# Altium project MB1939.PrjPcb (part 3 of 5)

## Sheet STM32_microcontroller_power.SchDoc: STM32_microcontroller_power
size A4; Date: Not used; ApprovedBy: Not used; CheckedBy: Not used; Author: Not used; CompanyName: STMicroelectronics; DrawnBy: Not used; Engineer: Not used; Organization: Not used; Address1: Not used; Address2: Not used; Address3: Not used; Address4: Not used; DocumentNumber: Not used; Revision: Not used; SheetNumber: 4; SheetTotal: 21
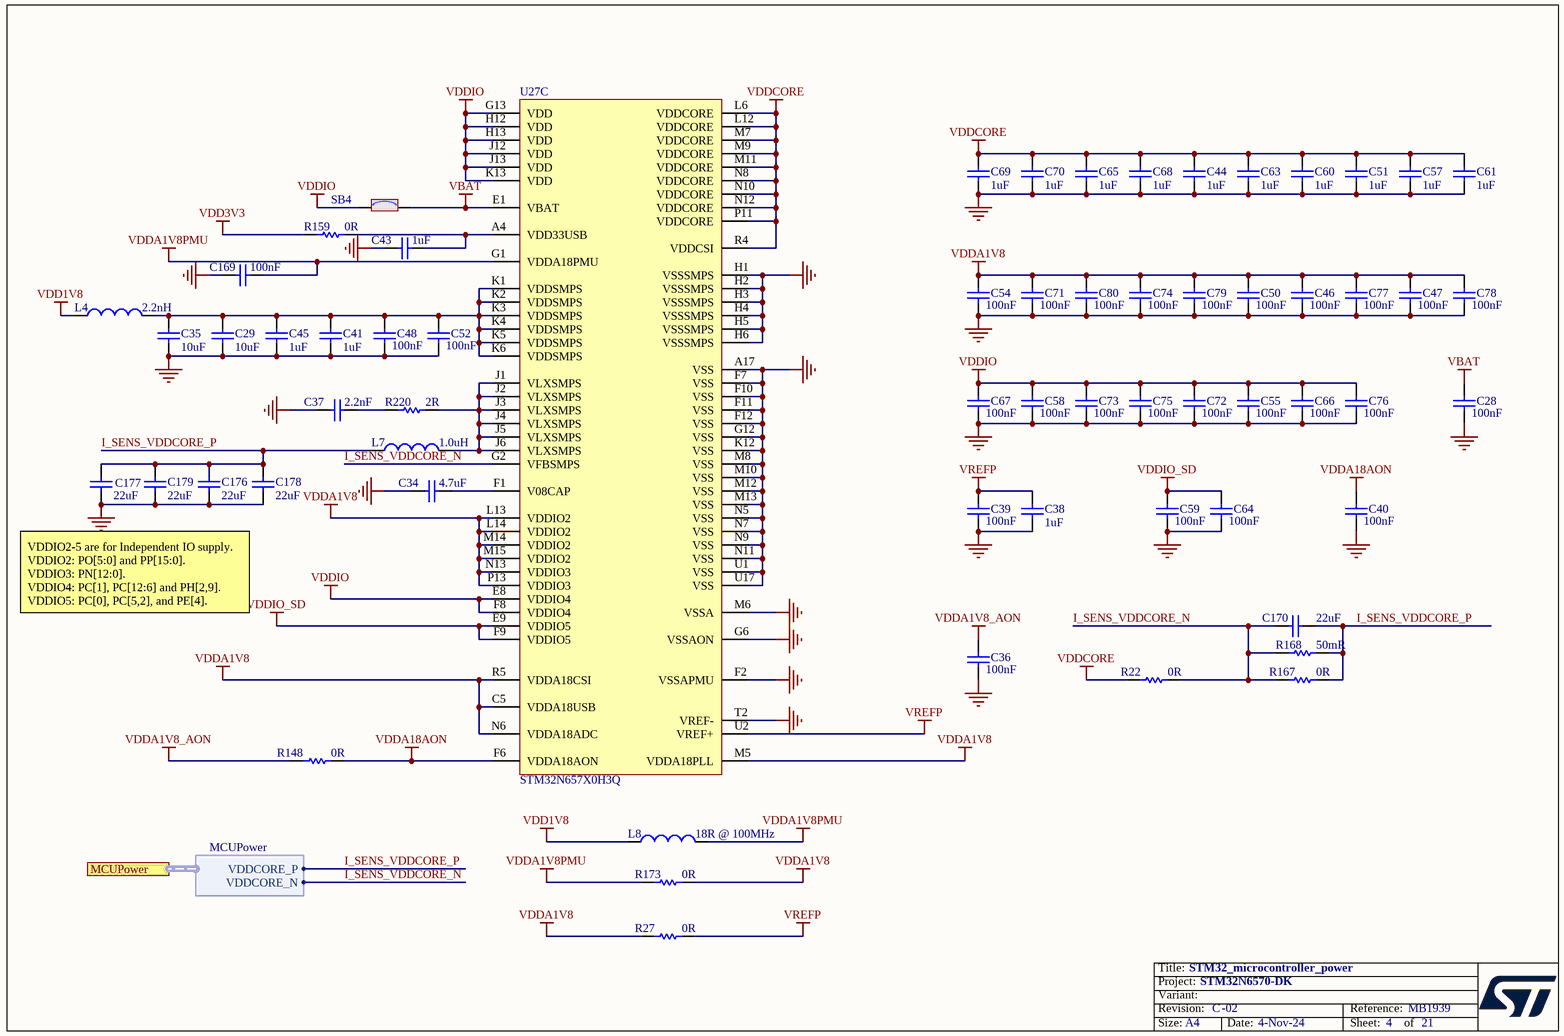
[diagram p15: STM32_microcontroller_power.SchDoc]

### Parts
C28  value 100nF  [C0201_MURATA_GRM033_H0P3]  (hidden comment: Capacitor)
C29  value 10uF  [C0402]  (hidden comment: Capacitor)
C34  value 4.7uF  [C0402]  (hidden comment: Capacitor)
C35  value 10uF  [C0402]  (hidden comment: Capacitor)
C36  value 100nF  [C0201_MURATA_GRM033_H0P3]  (hidden comment: Capacitor)
C37  value 2.2nF  [C0402]  (hidden comment: Capacitor)
C38  value 1uF  [C0201_MURATA_GRM033_H0P3]  (hidden comment: Capacitor)
C39  value 100nF  [C0201_MURATA_GRM033_H0P3]  (hidden comment: Capacitor)
C40  value 100nF  [C0201_MURATA_GRM033_H0P3]  (hidden comment: Capacitor)
C41  value 1uF  [C0201_MURATA_GRM033_H0P3]  (hidden comment: Capacitor)
C43  value 1uF  [C0201_MURATA_GRM033_H0P3]  (hidden comment: Capacitor)
C44  value 1uF  [C0201_MURATA_GRM033_H0P3]  (hidden comment: Capacitor)
C45  value 1uF  [C0201_MURATA_GRM033_H0P3]  (hidden comment: Capacitor)
C46  value 100nF  [C0201_MURATA_GRM033_H0P3]  (hidden comment: Capacitor)
C47  value 100nF  [C0201_MURATA_GRM033_H0P3]  (hidden comment: Capacitor)
C48  value 100nF  [C0201_MURATA_GRM033_H0P3]  (hidden comment: Capacitor)
C50  value 100nF  [C0201_MURATA_GRM033_H0P3]  (hidden comment: Capacitor)
C51  value 1uF  [C0201_MURATA_GRM033_H0P3]  (hidden comment: Capacitor)
C52  value 100nF  [C0201_MURATA_GRM033_H0P3]  (hidden comment: Capacitor)
C54  value 100nF  [C0201_MURATA_GRM033_H0P3]  (hidden comment: Capacitor)
C55  value 100nF  [C0201_MURATA_GRM033_H0P3]  (hidden comment: Capacitor)
C57  value 1uF  [C0201_MURATA_GRM033_H0P3]  (hidden comment: Capacitor)
C58  value 100nF  [C0201_MURATA_GRM033_H0P3]  (hidden comment: Capacitor)
C59  value 100nF  [C0201_MURATA_GRM033_H0P3]  (hidden comment: Capacitor)
C60  value 1uF  [C0201_MURATA_GRM033_H0P3]  (hidden comment: Capacitor)
C61  value 1uF  [C0201_MURATA_GRM033_H0P3]  (hidden comment: Capacitor)
C63  value 1uF  [C0201_MURATA_GRM033_H0P3]  (hidden comment: Capacitor)
C64  value 100nF  [C0201_MURATA_GRM033_H0P3]  (hidden comment: Capacitor)
C65  value 1uF  [C0201_MURATA_GRM033_H0P3]  (hidden comment: Capacitor)
C66  value 100nF  [C0201_MURATA_GRM033_H0P3]  (hidden comment: Capacitor)
C67  value 100nF  [C0201_MURATA_GRM033_H0P3]  (hidden comment: Capacitor)
C68  value 1uF  [C0201_MURATA_GRM033_H0P3]  (hidden comment: Capacitor)
C69  value 1uF  [C0201_MURATA_GRM033_H0P3]  (hidden comment: Capacitor)
C70  value 1uF  [C0201_MURATA_GRM033_H0P3]  (hidden comment: Capacitor)
C71  value 100nF  [C0201_MURATA_GRM033_H0P3]  (hidden comment: Capacitor)
C72  value 100nF  [C0201_MURATA_GRM033_H0P3]  (hidden comment: Capacitor)
C73  value 100nF  [C0201_MURATA_GRM033_H0P3]  (hidden comment: Capacitor)
C74  value 100nF  [C0201_MURATA_GRM033_H0P3]  (hidden comment: Capacitor)
C75  value 100nF  [C0201_MURATA_GRM033_H0P3]  (hidden comment: Capacitor)
C76  value 100nF  [C0201_MURATA_GRM033_H0P3]  (hidden comment: Capacitor)
C77  value 100nF  [C0201_MURATA_GRM033_H0P3]  (hidden comment: Capacitor)
C78  value 100nF  [C0201_MURATA_GRM033_H0P3]  (hidden comment: Capacitor)
C79  value 100nF  [C0201_MURATA_GRM033_H0P3]  (hidden comment: Capacitor)
C80  value 100nF  [C0201_MURATA_GRM033_H0P3]  (hidden comment: Capacitor)
C169  value 100nF  [C0201_MURATA_GRM033_H0P3]  (hidden comment: Capacitor)
C170  value 22uF  [C0603]  (hidden comment: Capacitor)
C176  value 22uF  [C0603]  (hidden comment: Capacitor)
C177  value 22uF  [C0603]  (hidden comment: Capacitor)
C178  value 22uF  [C0603]  (hidden comment: Capacitor)
C179  value 22uF  [C0603]  (hidden comment: Capacitor)
L4  value 2.2nH  [L0603]  (hidden comment: Inductor)
L7  value 1.0uH  [IND_MURATA_DFE201612P]  (hidden comment: Inductor)
L8  value 18R @ 100MHz  [IND_0603_LSMCA_H1P0]  (hidden comment: Inductor)
R22  value 0R  [R0603]  (hidden comment: Resistor)
R27  value 0R  [R0603]  (hidden comment: Resistor)
R148  value 0R  [R0805]  (hidden comment: Resistor)
R159  value 0R  [R0805]  (hidden comment: Resistor)
R167  value 0R  [R0603]  (hidden comment: Resistor)
R168  value 50mR  [R0603]  (hidden comment: Resistor)
R173  value 0R  [R0603]  (hidden comment: Resistor)
R220  value 2R  [R0402]  (hidden comment: Resistor)
SB4  SB_ON  [SOLDER-BRIDGE_R0603-0R]  (value not drawn)
U27  STM32N657X0H3Q  [ICC_VFBGA264_14X14_P080_SOCKET_IRONWOOD_SG-BGA-6112MF]  (part C of 3)

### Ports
MCUPower (harness MCUPower)

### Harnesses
MCUPower: VDDCORE_P, VDDCORE_N

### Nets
GND: C28.1 C29.1 C34.1 C35.1 C36.1 C37.1 C38.1 C39.1 C40.1 C41.1 C43.2 C44.1 C45.1 C46.1 C47.1 C48.1 C50.1 C51.1 C52.1 C54.1 C55.1 C57.1 C58.1 C59.1 C60.1 C61.1 C63.1 C64.1 C65.1 C66.1 C67.1 C68.1 C69.1 C70.1 C71.1 C72.1 C73.1 C74.1 C75.1 C76.1 C77.1 C78.1 C79.1 C80.1 C169.1 C176.1 C177.1 C178.1 C179.1 U27.A17(VSS) U27.F2(VSSAPMU) U27.F7(VSS) U27.F10(VSS) U27.F11(VSS) U27.F12(VSS) U27.G6(VSSAON) U27.G12(VSS) U27.H1(VSSSMPS) U27.H2(VSSSMPS) U27.H3(VSSSMPS) U27.H4(VSSSMPS) U27.H5(VSSSMPS) U27.H6(VSSSMPS) U27.K12(VSS) U27.M6(VSSA) U27.M8(VSS) U27.M10(VSS) U27.M12(VSS) U27.M13(VSS) U27.N5(VSS) U27.N7(VSS) U27.N9(VSS) U27.N11(VSS) U27.T2(VREF-) U27.U1(VSS) U27.U17(VSS)
VBAT: C28.2 SB4.2 U27.E1(VBAT)
VDD1V8: L4.1 L8.1
VDD3V3: R159.1
VDDA1V8: C46.2 C47.2 C50.2 C54.2 C71.2 C74.2 C77.2 C78.2 C79.2 C80.2 R27.1 R173.2 U27.C5(VDDA18USB) U27.L13(VDDIO2) U27.L14(VDDIO2) U27.M5(VDDA18PLL) U27.M14(VDDIO2) U27.M15(VDDIO2) U27.N6(VDDA18ADC) U27.N13(VDDIO3) U27.P13(VDDIO3) U27.R5(VDDA18CSI)
VDDA1V8_AON: C36.2 R148.1
VDDA1V8PMU: C169.2 L8.2 R173.1 U27.G1(VDDA18PMU)
VDDA18AON: C40.2 R148.2 U27.F6(VDDA18AON)
VDDCORE: C44.2 C51.2 C57.2 C60.2 C61.2 C63.2 C65.2 C68.2 C69.2 C70.2 R22.1 U27.L6(VDDCORE) U27.L12(VDDCORE) U27.M7(VDDCORE) U27.M9(VDDCORE) U27.M11(VDDCORE) U27.N8(VDDCORE) U27.N10(VDDCORE) U27.N12(VDDCORE) U27.P11(VDDCORE) U27.R4(VDDCSI)
VDDIO: C55.2 C58.2 C66.2 C67.2 C72.2 C73.2 C75.2 C76.2 SB4.1 U27.E8(VDDIO4) U27.F8(VDDIO4) U27.G13(VDD) U27.H12(VDD) U27.H13(VDD) U27.J12(VDD) U27.J13(VDD) U27.K13(VDD)
VDDIO_SD: C59.2 C64.2 U27.E9(VDDIO5) U27.F9(VDDIO5)
VREFP: C38.2 C39.2 R27.2 U27.U2(VREF+)
I_SENS_VDDCORE_N: C170.2 R22.2 R167.1 R168.1 U27.G2(VFBSMPS) ; port MCUPower.VDDCORE_N  [project net I_SENS_INT_VDDCORE_N]
I_SENS_VDDCORE_P: C170.1 C176.2 C177.2 C178.2 C179.2 L7.1 R167.2 R168.2 ; port MCUPower.VDDCORE_P  [project net I_SENS_INT_VDDCORE_P]
NetC29_2: C29.2 C35.2 C41.2 C45.2 C48.2 C52.2 L4.2 U27.K1(VDDSMPS) U27.K2(VDDSMPS) U27.K3(VDDSMPS) U27.K4(VDDSMPS) U27.K5(VDDSMPS) U27.K6(VDDSMPS)
NetC34_2: C34.2 U27.F1(V08CAP)
NetC37_2: C37.2 R220.1
NetC43_1: C43.1 R159.2 U27.A4(VDD33USB)
NetL7_2: L7.2 R220.2 U27.J1(VLXSMPS) U27.J2(VLXSMPS) U27.J3(VLXSMPS) U27.J4(VLXSMPS) U27.J5(VLXSMPS) U27.J6(VLXSMPS)

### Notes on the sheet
- VDDIO2-5 are for Independent IO supply.             VDDIO2: PO[5:0] and PP[15:0].                                       VDDIO3: PN[12:0].                                               VDDIO4: PC[1], PC[12:6] and PH[2,9].                                        VDDIO5: PC[0], PC[5,2], and PE[4].

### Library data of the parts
C28 C36 C39 C40 C46-C48 C50 C52 C54 C55 C58 C59 C64 C66 C67 C71-C80 C169 = MCD-01535: Capacitor, MLCC,100nF, 10V, X5R, +/-10%, 0201, T=0.3mm; Part_Preference: Recommended; Manufacturer: MURATA; Manufacturer_Part_Number: GRM033R61A104KE15; Order_Code_RS: 790-2742; Component_Country_Of_Origin: Japan°°; ShowFields: YES; ID: 3635
C29 C35 = MCD-01355: Capacitor, MLCC, 10uF, 4V, X5R, +/-20%, 0402, T=0.5mm; Part_Preference: Recommended; Manufacturer: MURATA; Manufacturer_Part_Number: GRM155R60G106ME44; Partial_Alternate_Internal_Part_Number: MCD-01716, MCD-02999; Order_Code_RS: 172-6477; Component_Country_Of_Origin: Japan°°; ShowFields: YES; ID: 3455
C34 = MCD-01356: Capacitor, MLCC, 4.7uF, 6V3, X5R, +/-20%, 0402, T=0.5mm; Part_Preference: Recommended; Manufacturer: MURATA; Manufacturer_Part_Number: GRM155R60J475ME47; Order_Code_RS: 814-5230; Component_Country_Of_Origin: Japan°°; ShowFields: YES; ID: 3456
C37 = MCD-02620: Capacitor, MLCC, 2.2nF, 50V, X7R, +/-10%, 0402, T=0.5mm; Part_Preference: Recommended; Manufacturer: YAGEO; Manufacturer_Part_Number: CC0402KRX7R9BB222; Order_Code_RS: 199-2257; ShowFields: YES; ID: 4726; Component_Country_Of_Origin: China
C38 C41 C43-C45 C51 C57 C60 C61 C63 C65 C68-C70 = MCD-02377: Capacitor, MLCC, 1uF, 6.3V, X5R, +/-20%, 0201, T=0,3mm; Part_Preference: Recommended; Manufacturer: MURATA; Manufacturer_Part_Number: GRM033R60J105MEA2; Order_Code_RS: 820-0643; Component_Country_Of_Origin: Japan°; ShowFields: YES; ID: 4483
C170 = MCD-00100: Capacitor, MLCC, 22uF, 6V3, X5R, +/-20%, 0603, T=0.8mm; Manufacturer_Part_Number: GRM188R60J226MEA0J; Manufacturer: MURATA; Part_Preference: Recommended; Component_Country_Of_Origin: Japan°°; ShowFields: YES; ID: 2766
C176-C179 = MCD-00100: Capacitor, MLCC, 22uF, 6V3, X5R, +/-20%, 0603, T=0.8mm; Part_Preference: Recommended; Manufacturer: MURATA; Manufacturer_Part_Number: GRM188R60J226MEA0J; Component_Country_Of_Origin: Japan°°; ShowFields: YES; ID: 2766
L4 = MCD-03222: Inductor, 2.2nH, +/-0.5nH, Irat=1.4Amax, 0R018, 0603, T=1mm, Qmin=25; Part_Preference: Recommended; Manufacturer: MURATA; Manufacturer_Part_Number: LQW18AN2N2D10D; ShowFields: YES; ID: 5338; Component_Country_Of_Origin: Malaysia
L7 = MCD-01491: Inductor, 1uH, +/-20%, Itemp= 2700mA, Isat= 3300mA, 0R054, 0806, T=1mm; Part_Preference: Recommended; Manufacturer: MURATA; Manufacturer_Part_Number: DFE201612P-1R0M; Order_Code_RS: 167-0602; Component_Country_Of_Origin: Japan°°; ShowFields: YES; ID: 3591
L8 = MCD-03956: Ferrite bead, 18R @ 100MHz, 750mA, 0R004, 0603, T=1mm; Part_Preference: Recommended; Manufacturer: TAIYO YUDEN; Manufacturer_Part_Number: LSMCA160808T180NGR; Component_Country_Of_Origin: Unknown; ShowFields: YES; ID: 6072
R22 R27 R167 R173 = MCD-00181: Resistor, 0R, 0603, +/- 0.5mR, 1/4W; Manufacturer_Part_Number: PMR03EZPJ000; Manufacturer: ROHM SEMICONDUCTOR; Part_Preference: Recommended; Component_Country_Of_Origin: Philippines, Thailand°°; ShowFields: YES; ID: 2691
R148 R159 = MCD-00179: Resistor, 0R, 0805, +/-5%, 1/8W; Part_Preference: Recommended; Manufacturer: YAGEO; Manufacturer_Part_Number: RC0805JR-070RL; Component_Country_Of_Origin: China; ShowFields: YES; ID: 2685
R168 = MCD-02233: Resistor, 50mR, 0603, +/-1%, 1/3W; Part_Preference: Recommended; Manufacturer: PANASONIC; Manufacturer_Part_Number: ERJ-3BWFR050V; Order_Code_RS: RA; Component_Country_Of_Origin: Japan; ShowFields: YES; ID: 4333
R220 = MCD-03930: Resistor, 2R, 0402, +/-1%, 1/16W; Part_Preference: Recommended; Manufacturer: YAGEO; Manufacturer_Part_Number: RC0402FR-072RL; ShowFields: YES; ID: 6046; Component_Country_Of_Origin: China
SB4 = MCD-00071: Resistor, 0R, SB0603, 5%, 0.1W; Manufacturer_Part_Number: RC0603JR-070RL; Manufacturer: YAGEO; Part_Preference: Recommended; Manufacturer_HQ_COO: Unknown; ShowFields: YES; ID: 2521; Order_Code_RS: 199-5647; Component_Country_Of_Origin: China
U27 = MCD-03176: Neural MCU, Arm® Cortex®-M55, 600-Gops ST Neural-ART Accelerator, Neo-Chrom 2.5D GPU, 4.2 MB contiguous SRAM; Part_Type: IC; Part_Preference: Recommended; Manufacturer: STMICROELECTRONICS; ShowFields: YES; ID: 5292; Component_Country_Of_Origin: Unknown

## Sheet Audio_Codec.SchDoc: Audio_Codec
size A4; Date: Not used; ApprovedBy: Not used; CheckedBy: Not used; Author: Not used; CompanyName: STMicroelectronics; DrawnBy: Not used; Engineer: Not used; Organization: Not used; Address1: Not used; Address2: Not used; Address3: Not used; Address4: Not used; DocumentNumber: Not used; Revision: Not used; SheetNumber: 15; SheetTotal: 21
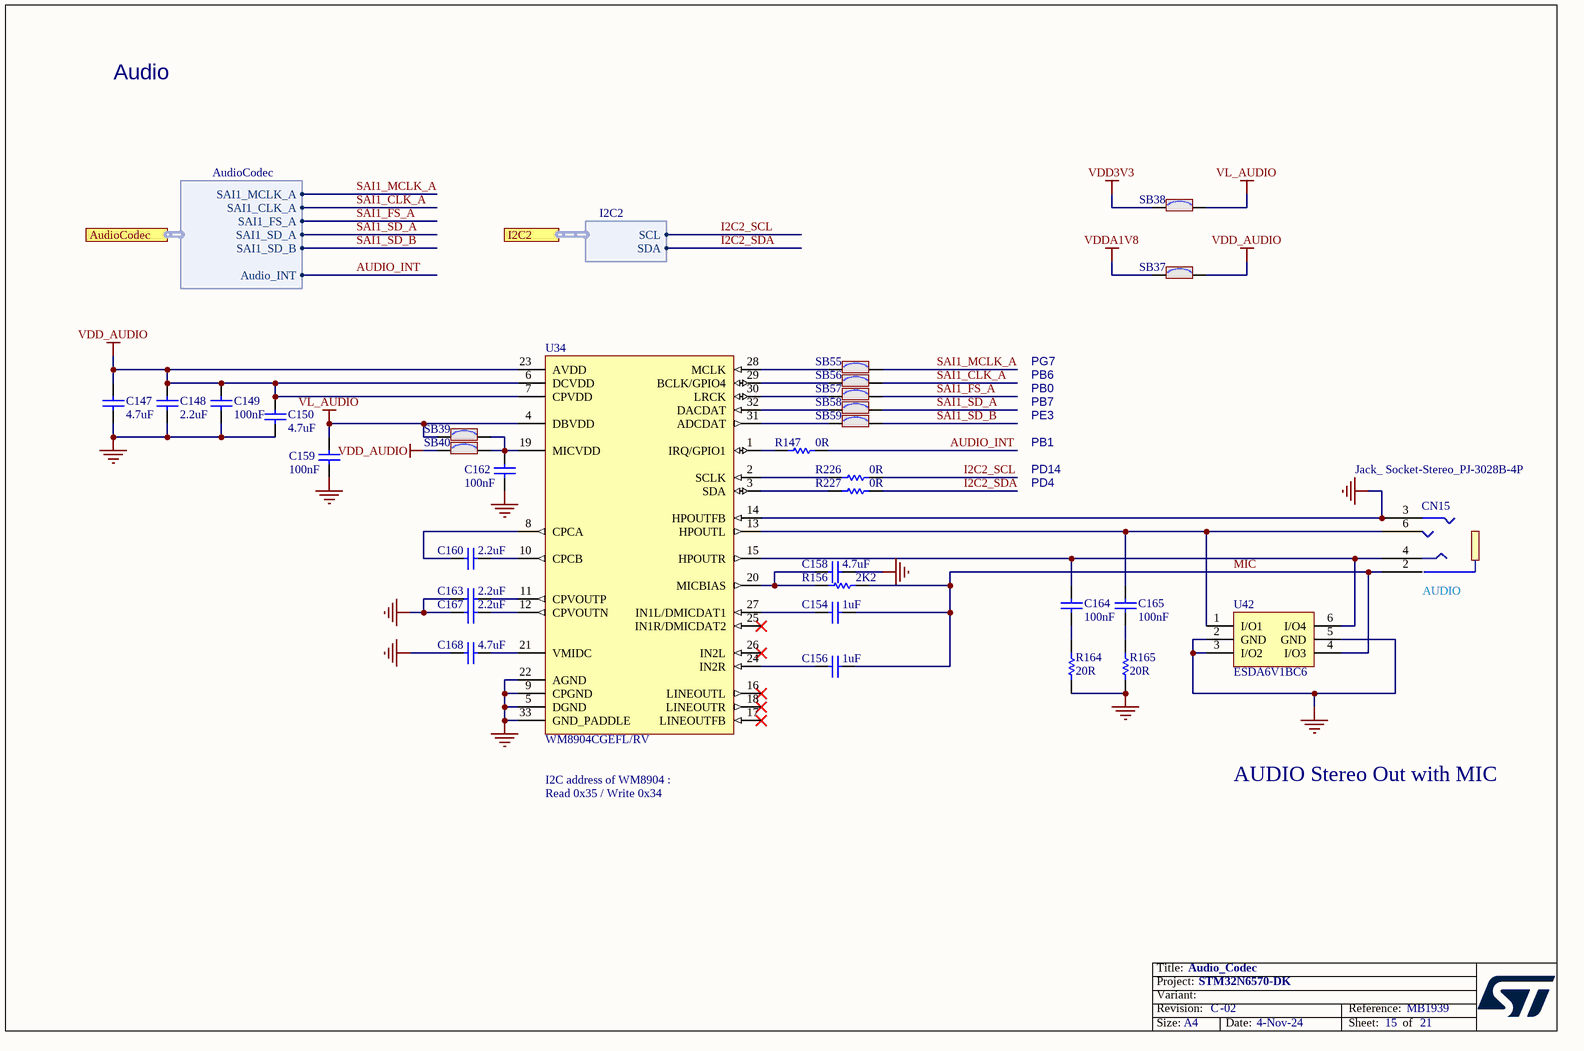
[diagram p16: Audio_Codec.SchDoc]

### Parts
C147  value 4.7uF  [C0603]  (hidden comment: Capacitor)
C148  value 2.2uF  [C0603]  (hidden comment: Capacitor)
C149  value 100nF  [C0402]  (hidden comment: Capacitor)
C150  value 4.7uF  [C0603]  (hidden comment: Capacitor)
C154  value 1uF  [C0603]  (hidden comment: Capacitor)
C156  value 1uF  [C0603]  (hidden comment: Capacitor)
C158  value 4.7uF  [C0603]  (hidden comment: Capacitor)
C159  value 100nF  [C0402]  (hidden comment: Capacitor)
C160  value 2.2uF  [C0603]  (hidden comment: Capacitor)
C162  value 100nF  [C0402]  (hidden comment: Capacitor)
C163  value 2.2uF  [C0603]  (hidden comment: Capacitor)
C164  value 100nF  [C0402]  (hidden comment: Capacitor)
C165  value 100nF  [C0402]  (hidden comment: Capacitor)
C167  value 2.2uF  [C0603]  (hidden comment: Capacitor)
C168  value 4.7uF  [C0603]  (hidden comment: Capacitor)
CN15  value Jack_ Socket-Stereo_PJ-3028B-4P  [CON_PHONE-JACK-3P5_HY_PJ3028B]  (hidden comment: Jack_PJ3028B-3_4P)
R147  value 0R  [R0603]  (hidden comment: Resistor)
R156  value 2K2  [R0402]  (hidden comment: Resistor)
R164  value 20R  [R0603]  (hidden comment: Resistor)
R165  value 20R  [R0603]  (hidden comment: Resistor)
R226  value 0R  [R0402]  (hidden comment: Resistor)
R227  value 0R  [R0402]  (hidden comment: Resistor)
SB37  SB_ON  [SOLDER-BRIDGE_R0402-0R]  (value not drawn)
SB38  SB_ON  [SOLDER-BRIDGE_R0402-0R]  (value not drawn)
SB39  SB_ON  [SOLDER-BRIDGE_R0402-0R]  (value not drawn)
SB40  SB_ON  [SOLDER-BRIDGE_R0402-0R]  (value not drawn)
SB55  SB_ON  [SOLDER-BRIDGE_R0402-0R]  (value not drawn)
SB56  SB_ON  [SOLDER-BRIDGE_R0402-0R]  (value not drawn)
SB57  SB_ON  [SOLDER-BRIDGE_R0402-0R]  (value not drawn)
SB58  SB_ON  [SOLDER-BRIDGE_R0402-0R]  (value not drawn)
SB59  SB_ON  [SOLDER-BRIDGE_R0402-0R]  (value not drawn)
U34  WM8904CGEFL/RV  [ICC_QFN32-EPAD_4X4_P040]
U42  ESDA6V1BC6  [ESD_SOT23-6L]

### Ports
AudioCodec (harness AudioCodec), I2C2 (harness I2C2)

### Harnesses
I2C2: SCL, SDA
AudioCodec: SAI1_MCLK_A, SAI1_CLK_A, SAI1_FS_A, SAI1_SD_A, SAI1_SD_B, Audio_INT

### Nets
GND: C147.1 C148.1 C149.1 C150.1 C158.2 C159.1 C162.1 C163.2 C167.2 C168.1 CN15.3 R164.1 R165.1 U34.5(DGND) U34.9(CPGND) U34.14(HPOUTFB) U34.22(AGND) U34.33(GND_PADDLE) U42.2(GND) U42.3(I/O2) U42.5(GND)
VDD3V3: SB38.1
VDD_AUDIO: C147.2 C148.2 C149.2 C150.2 SB37.2 SB40.1 U34.6(DCVDD) U34.7(CPVDD) U34.23(AVDD)
VDDA1V8: SB37.1
VL_AUDIO: C159.2 SB38.2 SB39.1 U34.4(DBVDD)
AUDIO_INT: R147.2 ; port AudioCodec.Audio_INT
I2C2_SCL: R226.2 ; port I2C2.SCL
I2C2_SDA: R227.2 ; port I2C2.SDA
MIC: C154.2 C156.2 CN15.2 R156.1 U42.4(I/O3)
SAI1_CLK_A: SB56.2 ; port AudioCodec.SAI1_CLK_A  [project net PB6]
SAI1_FS_A: SB57.2 ; port AudioCodec.SAI1_FS_A  [project net PB0]
SAI1_MCLK_A: SB55.2 ; port AudioCodec.SAI1_MCLK_A  [project net PG7]
SAI1_SD_A: SB58.2 ; port AudioCodec.SAI1_SD_A  [project net PB7]
SAI1_SD_B: SB59.2 ; port AudioCodec.SAI1_SD_B  [project net PE3]
NetC154_1: C154.1 U34.27(IN1L/DMICDAT1)
NetC156_1: C156.1 U34.24(IN2R)
NetC158_1: C158.1 R156.2 U34.20(MICBIAS)
NetC160_1: C160.1 U34.10(CPCB)
NetC160_2: C160.2 U34.8(CPCA)
NetC162_2: C162.2 SB39.2 SB40.2 U34.19(MICVDD)
NetC163_1: C163.1 U34.11(CPVOUTP)
NetC164_1: C164.1 CN15.4 U34.15(HPOUTR) U42.6(I/O4)
NetC164_2: C164.2 R164.2
NetC165_1: C165.1 CN15.6 U34.13(HPOUTL) U42.1(I/O1)
NetC165_2: C165.2 R165.2
NetC167_1: C167.1 U34.12(CPVOUTN)
NetC168_2: C168.2 U34.21(VMIDC)
NetR147_1: R147.1 U34.1(IRQ/GPIO1)
NetR226_1: R226.1 U34.2(SCLK)
NetR227_1: R227.1 U34.3(SDA)
NetSB55_1: SB55.1 U34.28(MCLK)
NetSB56_1: SB56.1 U34.29(BCLK/GPIO4)
NetSB57_1: SB57.1 U34.30(LRCK)
NetSB58_1: SB58.1 U34.32(DACDAT)
NetSB59_1: SB59.1 U34.31(ADCDAT)

Not connected (* = marked no-connect by the designer): U34 16(LINEOUTL)* 17(LINEOUTFB)* 18(LINEOUTR)* 25(IN1R/DMICDAT2)* 26(IN2L)*

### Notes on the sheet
- Audio
- PG7
- PB6
- PB0
- PB7
- PE3
- PB1
- PD14
- PD4
- (near CN15) AUDIO
- I2C address of WM8904 :
- AUDIO Stereo Out with MIC
- Read 0x35 / Write 0x34
- Title:
- Project:
- Size:
- Revision:
- Variant:
- A4
- -
- Date:
- Reference:
- Sheet:
- of

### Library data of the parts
C147 C150 C158 C168 = MCD-00009: Capacitor, MLCC, 4.7uF, 16V, X5R, +/-10%, 0603, T=0.8mm; Part_Preference: Recommended; Manufacturer: YAGEO; Manufacturer_Part_Number: CC0603KRX5R7BB475; Partial_Alternate_Internal_Part_Number: MCD-03565; Component_Country_Of_Origin: China; Alternate_EMS: A; ShowFields: YES; ID: 2471
C148 C160 C163 C167 = MCD-00012: Capacitor, MLCC, 2.2uF, 10V, X5R, +/- 10%, 0603, T=0.8mm; BMS_Part_Number: 9142010; Part_Preference: Recommended; Manufacturer: YAGEO; Manufacturer_Part_Number: CC0603KRX5R6BB225; Partial_Alternate_Internal_Part_Number: MCD-00551; Order_Code_RS: 2370679; Component_Country_Of_Origin: China; ShowFields: YES; ID: 2467
C149 C159 C162 C164 C165 = MCD-00006: Capacitor, MLCC, 100nF, 16V, X7R, +/-10%, 0402, T=0.5mm; Manufacturer_Part_Number: CC0402KRX7R7BB104; Manufacturer: YAGEO; Part_Preference: Recommended; Partial_Alternate_Internal_Part_Number: MCD-03299; Order_Code_RS: 9402047; Component_Country_Of_Origin: China; ShowFields: YES; ID: 2474
C154 C156 = MCD-00010: Capacitor, MLCC, 1uF, 16V, X5R, +/-10%, 0603, T=0.8mm; Manufacturer_Part_Number: CC0603KRX5R7BB105; Manufacturer: YAGEO; Part_Preference: Recommended; Order_Code_RS: 2370680; Component_Country_Of_Origin: China; ShowFields: YES; ID: 2470
CN15 = MCD-00263: Jack_ Socket-Stereo, 3.5mm, 4 pins, RA, SMD, T=5mm; Part_Type: Connector; Manufacturer_Part_Number: PJ-3028B-4P; Manufacturer: QIAOD; Part_Preference: Recommended; Component_Country_Of_Origin: Unknown; ShowFields: YES; ID: 2608
R147 = MCD-00056: Resistor, 0R, 0603, +/-5%, 1/10W; Part_Preference: Recommended; Manufacturer: YAGEO; Manufacturer_Part_Number: RC0603JR-070RL; Order_Code_RS: 9233130RL; Component_Country_Of_Origin: China; ShowFields: YES; ID: 2536
R156 = MCD-00057: Resistor, 2K2, 0402, +/-1%, 1/16W; Manufacturer_Part_Number: RC0402FR-072K2L; Manufacturer: YAGEO; Part_Preference: Recommended; Order_Code_RS: 9239278; Component_Country_Of_Origin: China; ShowFields: YES; ID: 2534
R164 R165 = MCD-00345: Resistor, 20R, 0603, +/-1%, 1/10W; Part_Preference: Recommended; Manufacturer: YAGEO; Manufacturer_Part_Number: RC0603FR-0720RL; Component_Country_Of_Origin: China; ShowFields: YES; ID: 2933
R226 R227 = MCD-00052: Resistor, 0R, 0402, +/-5%, 1/16W; Manufacturer_Part_Number: RC0402JR-070RL; Manufacturer: YAGEO; Part_Preference: Recommended; Order_Code_RS: 9232516RL; Component_Country_Of_Origin: China; ShowFields: YES; ID: 2540
SB37-SB40 SB55-SB59 = MCD-01618: Resistor, 0R, SB0402, 5%, 0.063W; Manufacturer_Part_Number: RC0402JR-070RL; Manufacturer: YAGEO; Part_Preference: Recommended; Order_Code_RS: 618-5804; Component_Country_Of_Origin: China; ShowFields: YES; ID: 3718
U34 = MCD-03825: Audio Codec, Ultra Low-Power Codec for Portable Audio Applications; Part_Type: IC; Part_Preference: Recommended; Manufacturer: CIRRUS LOGIC; ShowFields: YES; ID: 5941; Component_Country_Of_Origin: Taiwan
U42 = MCD-00247: Diode, ESD Transil, 5V, 1uA, 8V, SOT23-6; Manufacturer: STMICROELECTRONICS; BMS_Part_Number: 9179038; Part_Preference: Recommended; Manufacturer_HQ_COO: EU; Component_Country_Of_Origin: China; ShowFields: YES; ID: 2624; Order_Code_RS: 248-805

## Sheet USB1_DRP.SchDoc: USB1_DRP
size A3; Date: Not used; ApprovedBy: Not used; CheckedBy: Not used; Author: Not used; CompanyName: STMicroelectronics; DrawnBy: Not used; Engineer: Not used; Organization: Not used; Address1: Not used; Address2: Not used; Address3: Not used; Address4: Not used; DocumentNumber: Not used; Revision: Not used; SheetNumber: 17; SheetTotal: 21
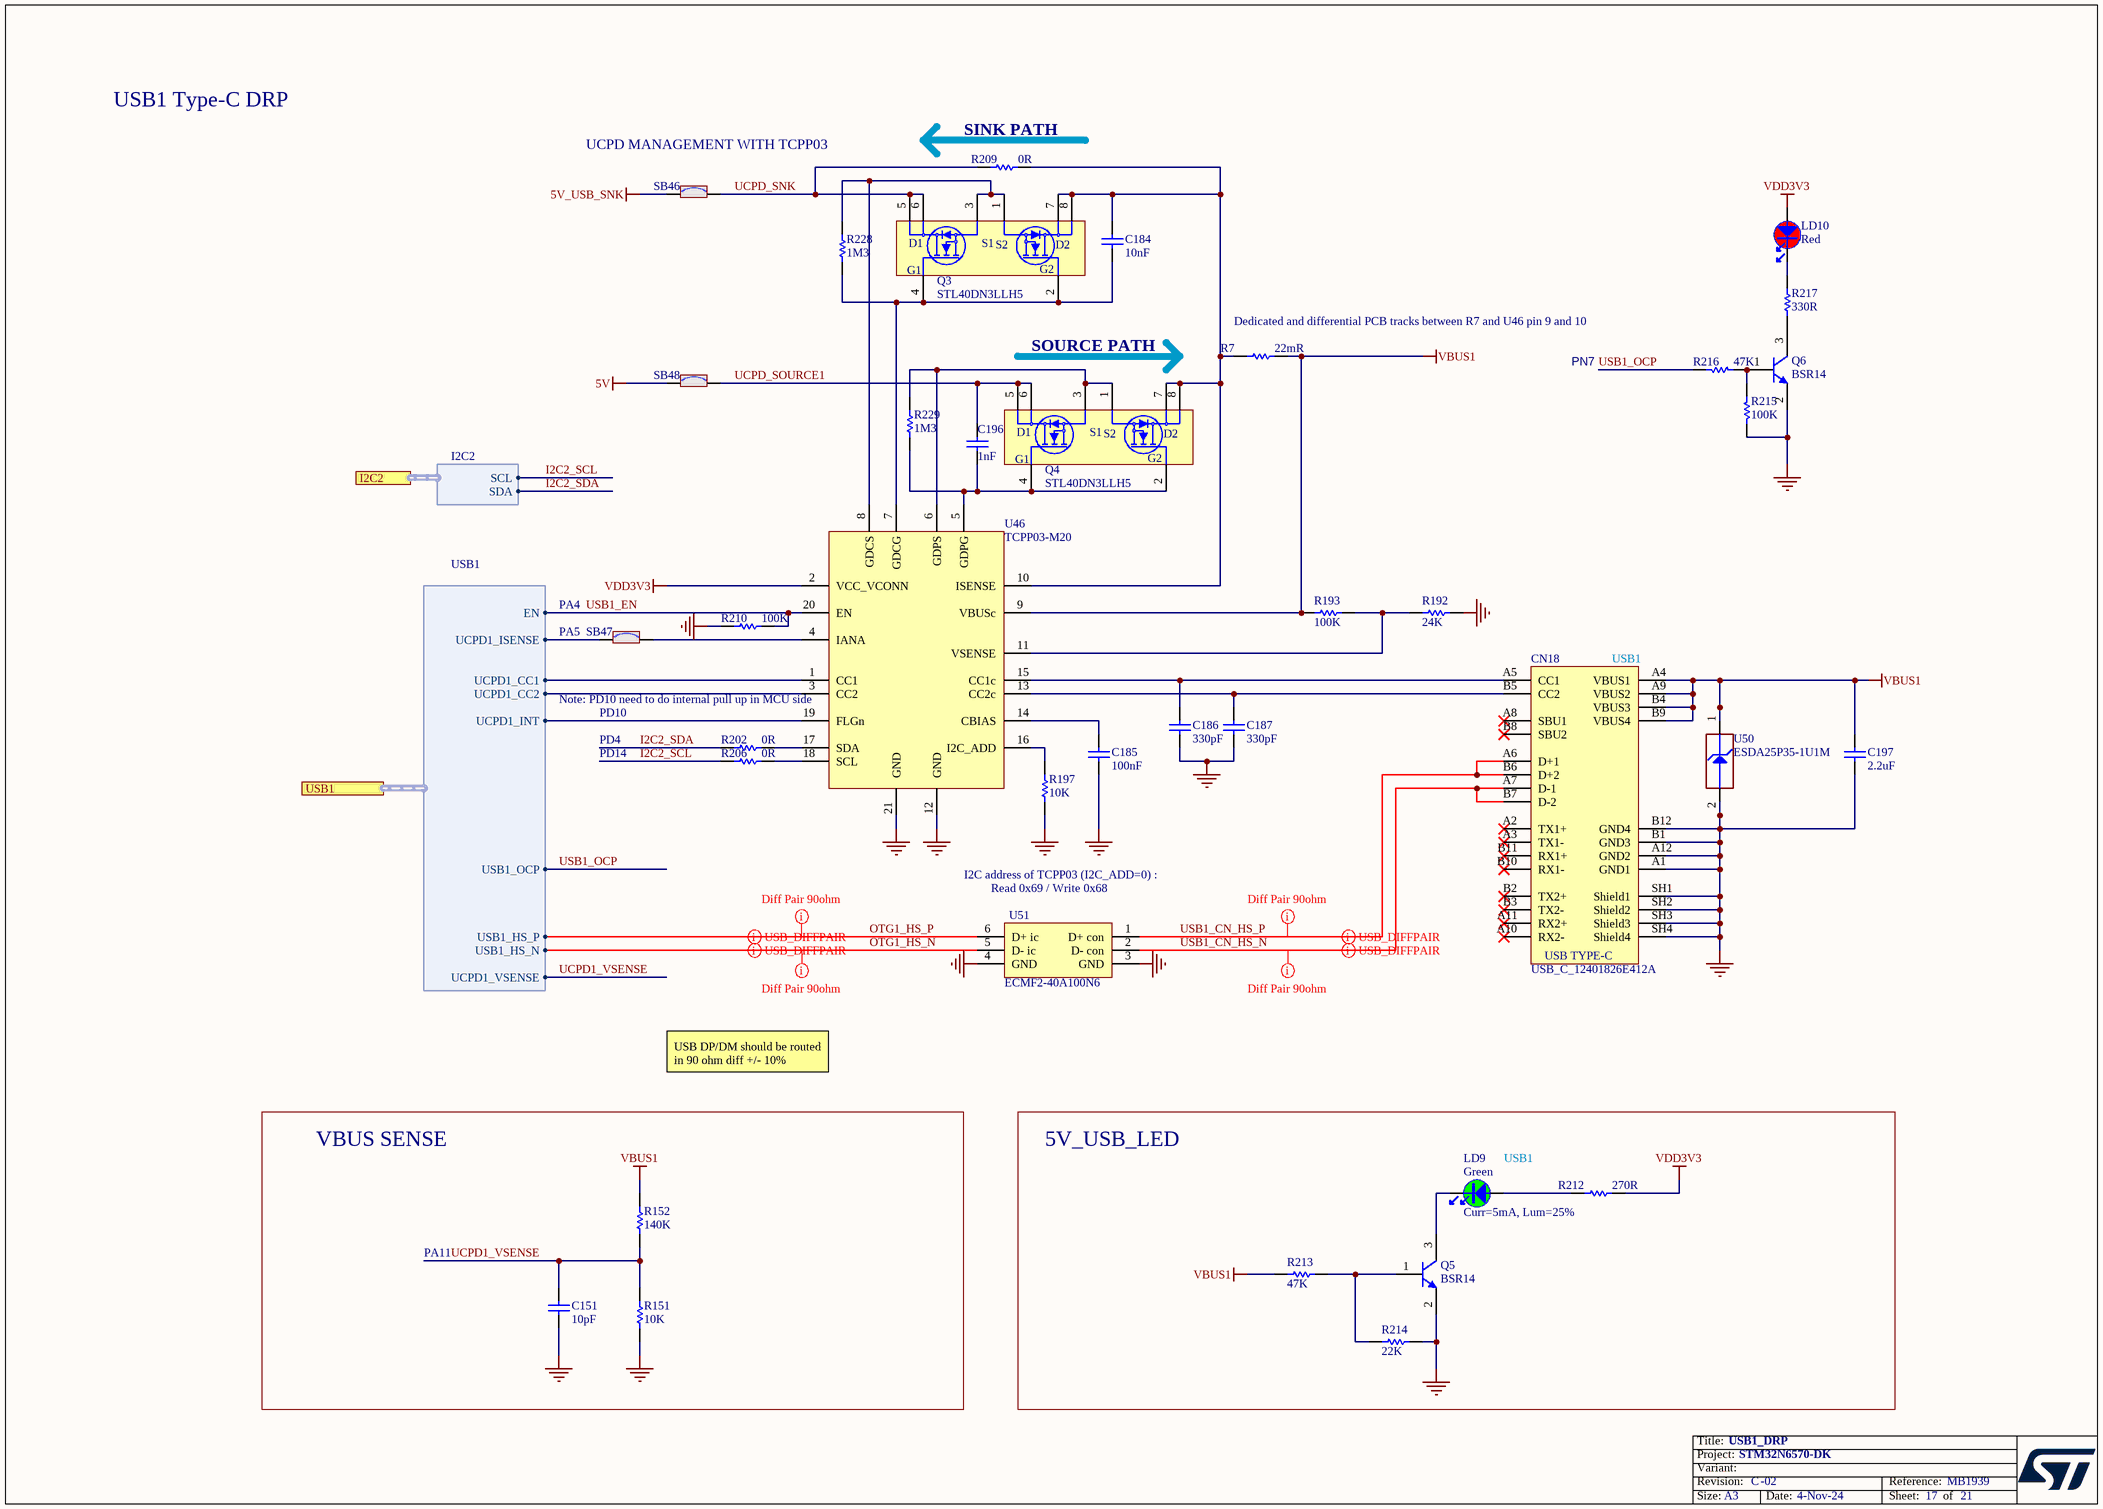
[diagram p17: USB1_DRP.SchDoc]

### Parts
C151  value 10pF  [C0402]  (hidden comment: Capacitor)
C184  value 10nF  [C0402]  (hidden comment: Capacitor)
C185  value 100nF  [C0603]  (hidden comment: Capacitor)
C186  value 330pF  [C0402]  (hidden comment: Capacitor)
C187  value 330pF  [C0402]  (hidden comment: Capacitor)
C196  value 1nF  [C0805_H0P6]  (hidden comment: Capacitor)
C197  value 2.2uF  [C0805]  (hidden comment: Capacitor)
CN18  value USB_C_12401826E412A  [CON_USB-TYPEC_AMPHENOL_12401826E412A]  (hidden comment: USB_TYPE_C_Receptacle)
LD9  value Green  [LED_0603_OSRAM_LG-Q396-PS-35_GREEN_1A2K_H0P4]  (hidden comment: LED_green)
LD10  value Red  [LED_0603_VISHAY_VLMS1300-GS08_RED_1A2K_H0P8]  (hidden comment: LED_red)
Q3  STL40DN3LLH5  [PowerFLAT_5x6]
Q4  STL40DN3LLH5  [PowerFLAT_5x6]
Q5  value BSR14  [NPN_SOT23]  (hidden comment: 9013-SOT23)
Q6  value BSR14  [NPN_SOT23]  (hidden comment: 9013-SOT23)
R7  value 22mR  [R0603]  (hidden comment: Resistor)
R151  value 10K  [R0402]  (hidden comment: Resistor)
R152  value 140K  [R0402]  (hidden comment: Resistor)
R192  value 24K  [R0402]  (hidden comment: Resistor)
R193  value 100K  [R0402]  (hidden comment: Resistor)
R197  value 10K  [R0402]  (hidden comment: Resistor)
R202  value 0R  [R0402]  (hidden comment: Resistor)
R206  value 0R  [R0402]  (hidden comment: Resistor)
R209  value 0R  [R0603]  (hidden comment: Resistor)
R210  value 100K  [R0402]  (hidden comment: Resistor)
R212  value 270R  [R0402]  (hidden comment: Resistor)
R213  value 47K  [R0402]  (hidden comment: Resistor)
R214  value 22K  [R0603]  (hidden comment: Resistor)
R215  value 100K  [R0402]  (hidden comment: Resistor)
R216  value 47K  [R0402]  (hidden comment: Resistor)
R217  value 330R  [R0402]  (hidden comment: Resistor)
R228  value 1M3  [R0402]  (hidden comment: Resistor)
R229  value 1M3  [R0402]  (hidden comment: Resistor)
SB46  SB_ON  [SOLDER-BRIDGE_R0603-0R]  (value not drawn)
SB47  SB_ON  [SOLDER-BRIDGE_R0603-0R]  (value not drawn)
SB48  SB_ON  [SOLDER-BRIDGE_R0603-0R]  (value not drawn)
U46  TCPP03-M20  [ICC_QFN20-EPAD_4X4_P050]
U50  value ESDA25P35-1U1M  [ESD_QFN1610_2N_1K_2A]  (hidden comment: ESD-TRANSIL)
U51  ECMF2-40A100N6  [ESD_UQFN-6L_1P45X1P4_P040]

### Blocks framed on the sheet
VBUS SENSE: C151 R151 R152
5V_USB_LED: LD9 Q5 R212-R214

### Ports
I2C2 (harness I2C2), USB1 (harness USB1)

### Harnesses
USB1: UCPD1_CC1, UCPD1_CC2, UCPD1_ISENSE, USB1_HS_P, USB1_HS_N, UCPD1_VSENSE, UCPD1_INT, USB1_OCP, EN
I2C2: SCL, SDA

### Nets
5V: SB48.1
5V_USB_SNK: SB46.1
GND: C151.1 C185.2 C186.1 C187.1 C197.1 CN18.A1(GND1) CN18.A12(GND2) CN18.B1(GND3) CN18.B12(GND4) CN18.SH1(Shield1) CN18.SH2(Shield2) CN18.SH3(Shield3) CN18.SH4(Shield4) Q5.2(E) Q6.2(E) R151.1 R192.2 R197.2 R210.1 R214.2 R215.1 U46.12(GND) U46.21(GND) U50.2(GND) U51.3(GND) U51.4(GND)
VBUS1: C197.2 CN18.A4(VBUS1) CN18.A9(VBUS2) CN18.B4(VBUS3) CN18.B9(VBUS4) R7.2 R152.2 R193.1 R213.1 U46.9(VBUSc) U50.1(IO1)
VDD3V3: LD10.1 R212.1 U46.2(VCC_VCONN)
ARD_A0: SB47.1 ; port USB1.UCPD1_ISENSE
I2C2_SCL: R206.1 ; port I2C2.SCL
I2C2_SDA: R202.1 ; port I2C2.SDA
OTG1_HS_N: U51.5(D-_ic) ; port USB1.USB1_HS_N
OTG1_HS_P: U51.6(D+_ic) ; port USB1.USB1_HS_P
PD10: U46.19(FLGn) ; port USB1.UCPD1_INT
UCPD1_CC1: U46.1(CC1) ; port USB1.UCPD1_CC1
UCPD1_CC2: U46.3(CC2) ; port USB1.UCPD1_CC2
UCPD1_VSENSE: C151.2 R151.2 R152.1 ; port USB1.UCPD1_VSENSE  [project net PA11]
UCPD_SNK: Q3.5(D1) Q3.6(D1) R209.1 SB46.2
UCPD_SOURCE1: C196.1 Q4.5(D1) Q4.6(D1) SB48.2
USB1_CN_HS_N: CN18.A7(D-1) CN18.B7(D-2) U51.2(D-_con)
USB1_CN_HS_P: CN18.A6(D+1) CN18.B6(D+2) U51.1(D+_con)
USB1_EN: R210.2 U46.20(EN) ; port USB1.EN  [project net PA4]
USB1_OCP: R216.2 ; port USB1.USB1_OCP  [project net PN7]
NetC184_1: C184.1 Q3.7(D2) Q3.8(D2) Q4.7(D2) Q4.8(D2) R7.1 R209.2 U46.10(ISENSE)
NetC184_2: C184.2 Q3.2(G2) Q3.4(G1) R228.1 U46.7(GDCG)
NetC185_1: C185.1 U46.14(CBIAS)
NetC186_2: C186.2 CN18.A5(CC1) U46.15(CC1c)
NetC187_2: C187.2 CN18.B5(CC2) U46.13(CC2c)
NetC196_2: C196.2 Q4.2(G2) Q4.4(G1) R229.1 U46.5(GDPG)
NetLD9_1: LD9.1 R212.2
NetLD9_2: LD9.2 Q5.3(C)
NetLD10_2: LD10.2 R217.2
NetQ3_1: Q3.1(S2) Q3.3(S1) R228.2 U46.8(GDCS)
NetQ4_1: Q4.1(S2) Q4.3(S1) R229.2 U46.6(GDPS)
NetQ5_1: Q5.1(B) R213.2 R214.1
NetQ6_1: Q6.1(B) R215.2 R216.1
NetQ6_3: Q6.3(C) R217.1
NetR192_1: R192.1 R193.2 U46.11(VSENSE)
NetR197_1: R197.1 U46.16(I2C_ADD)
NetR202_2: R202.2 U46.17(SDA)
NetR206_2: R206.2 U46.18(SCL)
NetSB47_2: SB47.2 U46.4(IANA)

Not connected (* = marked no-connect by the designer): CN18 A2(TX1+)* A3(TX1-)* A8(SBU1)* A10(RX2-)* A11(RX2+)* B2(TX2+)* B3(TX2-)* B8(SBU2)* B10(RX1-)* B11(RX1+)*

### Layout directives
mark named Diff Pair 90ohm: OTG1_HS_N, OTG1_HS_P, USB1_CN_HS_N, USB1_CN_HS_P
differential pair: OTG1_HS_N, OTG1_HS_P, USB1_CN_HS_N, USB1_CN_HS_P

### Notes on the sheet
- USB1 Type-C DRP
- (near SB46) UCPD MANAGEMENT WITH TCPP03
- (near R209) SINK PATH
- SOURCE PATH
- (near R7) Dedicated and differential PCB tracks between R7 and U46 pin 9 and 10
- PN7
- (near SB47) PA5
- (near SB47) PA4
- (near U46) Note: PD10 need to do internal pull up in MCU side
- PD10
- (near CN18) USB1
- PD14
- PD4
- I2C address of TCPP03 (I2C_ADD=0) :
- (near U51) Read 0x69 / Write 0x68
- USB DP/DM should be routed in 90 ohm diff +/- 10%
- (near LD9) USB1
- PA11
- Curr=5mA, Lum=25%

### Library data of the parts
C151 = MCD-00015: Capacitor, MLCC, 10pF, 50V, NPO, +/-5%, 0402, T=0.5mm; Manufacturer_Part_Number: CC0402JRNPO9BN100; Manufacturer: YAGEO; Part_Preference: Recommended; Order_Code_RS: 3019160RL; Component_Country_Of_Origin: China; ShowFields: YES; ID: 2465
C184 = MCD-02198: Capacitor, MLCC, 10nF, 50V, X7R, +/-10%, 0402, T=0.5mm; Manufacturer_Part_Number: CC0402KRX7R9BB103; Manufacturer: YAGEO; Part_Preference: Recommended; Order_Code_RS: 6169644; Component_Country_Of_Origin: China; ShowFields: YES; ID: 4298
C185 = MCD-01099: Capacitor, MLCC, 100nF, 50V, X7R, +/-10%, 0603, T=0.8mm; Manufacturer_Part_Number: CC0603KRX7R9BB104; Manufacturer: YAGEO; BMS_Part_Number: 9142278; Part_Preference: Recommended; Order_Code_RS: 669-8767; Component_Country_Of_Origin: China; ShowFields: YES; ID: 3397
C186 C187 = MCD-01579: Capacitor, MLCC, 330pF, 50V, NPO, +/-5%, 0402, T=0.5mm; Part_Preference: Recommended; Manufacturer: YAGEO; Manufacturer_Part_Number: CC0402JRNPO9BN331; Component_Country_Of_Origin: China; ShowFields: YES; ID: 3679
C196 = MCD-01549: Capacitor, MLCC, 1nF, 50V, X7R,+/-10%, 0805, T=0.6mm; Manufacturer_Part_Number: CC0805KRX7R9BB102; Manufacturer: YAGEO; Part_Preference: Recommended; Order_Code_RS: 669-8855; Component_Country_Of_Origin: China; ShowFields: YES; ID: 3649
C197 = MCD-02372: Capacitor, MLCC, 2.2uF, 25V, X7R, +/-10%, 0805, T=1,25mm; Part_Preference: Recommended; Manufacturer: MURATA; Manufacturer_Part_Number: GRM21BR71E225KE11L; Partial_Alternate_Internal_Part_Number: MCD-04185; Component_Country_Of_Origin: Japan°; ShowFields: YES; ID: 4478
CN18 = MCD-03232: USB_TypeC, 24 pins, RA, SMD, T=2.96mm; Part_Type: Connector; Part_Preference: Recommended; Manufacturer: AMPHENOL CS; Manufacturer_Part_Number: 12401826E412A; Component_Country_Of_Origin: China°; ShowFields: YES; ID: 5348
LD9 = MCD-00588: LED, Green, 2V, 20mA, 0603; Part_Type: Display; Manufacturer_Part_Number: LG Q396-PS-35; Manufacturer: OSRAM OPTO SEMICONDUCTORS; Part_Preference: Recommended; Partial_Alternate_Internal_Part_Number: MCD-02400, MCD-03155, MCD-02901; Component_Country_Of_Origin: Unknown; ShowFields: YES; ID: 3155
LD10 = MCD-00587: LED, Red, 2V, 20mA, 0603; Manufacturer_Part_Number: VLMS1300-GS08; Manufacturer: VISHAY; Part_Type: Display; Part_Preference: Recommended; Full_Alternate_Internal_Part_Number: MCD-02401; Component_Country_Of_Origin: China; ShowFields: YES; ID: 3154
Q3 Q4 = MCD-02152: Transistor, MOSFET, N-CH, 30V, 40A, PowerFLAT-8; Manufacturer: STMICROELECTRONICS; Part_Preference: Forbidden; Manufacturer_HQ_COO: EU; Component_Country_Of_Origin: China; ShowFields: YES; ID: 4252
Q5 Q6 = MCD-00073: Transistor, NPN, 40V, 800mA, SOT23; Manufacturer: ON SEMICONDUCTOR; Part_Preference: Recommended; Partial_Alternate_Internal_Part_Number: MCD-01737, MCD-03305, , MCD-02988; Component_Country_Of_Origin: Unknown; ShowFields: YES; ID: 2519
R7 = MCD-02232: Resistor, 22mR, 0603, +/-1%, 1/3W; Part_Preference: Recommended; Manufacturer: PANASONIC; Manufacturer_Part_Number: ERJ-3BWFR022V; Order_Code_RS: 763-8671P; Component_Country_Of_Origin: Japan; ShowFields: YES; ID: 4332
R151 = MCD-00053: Resistor, 10K, 0402, +/-1%, 1/16W; BMS_Part_Number: 9131590; Part_Preference: Recommended; Manufacturer: YAGEO; Manufacturer_Part_Number: RC0402FR-0710KL; Order_Code_RS: 9239359; Component_Country_Of_Origin: China; ShowFields: YES; ID: 2539
R152 = MCD-02335: Resistor, 140K, 0402, +/-1%, 1/16W; Part_Preference: Recommended; Manufacturer: YAGEO; Manufacturer_Part_Number: RC0402FR-07140KL; Component_Country_Of_Origin: China; ShowFields: YES; ID: 4441
R192 = MCD-00435: Resistor, 24K, 0402, +/-1%, 1/16W; Part_Preference: Recommended; Manufacturer: YAGEO; Manufacturer_Part_Number: RC0402FR-0724KL; Component_Country_Of_Origin: China; ShowFields: YES; ID: 2845
R193 = MCD-02265: Resistor,100K,0402,0.5%,1/16W; Part_Preference: Recommended; Manufacturer: YAGEO; Manufacturer_Part_Number: RC0402DR-07100KL; Component_Country_Of_Origin: China; ShowFields: YES; ID: 4365
R197 = MCD-00053: Resistor, 10K, 0402, +/-1%, 1/16W; Manufacturer_Part_Number: RC0402FR-0710KL; Manufacturer: YAGEO; BMS_Part_Number: 9131590; Part_Preference: Recommended; Order_Code_RS: 9239359; Component_Country_Of_Origin: China; ShowFields: YES; ID: 2539
R202 R206 = MCD-00052: as R226 on sheet Audio_Codec
R209 = MCD-00181: as R22 on sheet STM32_microcontroller_power
R210 = MCD-00059: Resistor, 100K, 0402, +/-1%, 1/16W; Manufacturer_Part_Number: RC0402FR-07100KL; Manufacturer: YAGEO; Part_Preference: Recommended; Partial_Alternate_Internal_Part_Number: MCD-03301; Order_Code_RS: 2421891; Component_Country_Of_Origin: China; ShowFields: YES; ID: 2533
R212 = MCD-00441: Resistor, 270R, 0402, +/-1%, 1/16W; Manufacturer_Part_Number: RC0402FR-07270RL; Manufacturer: YAGEO; Part_Preference: Recommended; Component_Country_Of_Origin: China; ShowFields: YES; ID: 2838
R213 R216 = MCD-00063: Resistor, 47K, 0402, +/-1%, 1/16W; Manufacturer_Part_Number: RC0402FR-0747KL; Manufacturer: YAGEO; Part_Preference: Recommended; Order_Code_RS: 9239430; Component_Country_Of_Origin: China; ShowFields: YES; ID: 2528
R214 = MCD-00430: Resistor, 22K, 0603, +/-1%, 1/10W; Manufacturer_Part_Number: RC0603FR-0722KL; Manufacturer: YAGEO; Part_Preference: Recommended; Component_Country_Of_Origin: China; ShowFields: YES; ID: 2847
R215 = MCD-00059: Resistor, 100K, 0402, +/-1%, 1/16W; Part_Preference: Recommended; Manufacturer: YAGEO; Manufacturer_Part_Number: RC0402FR-07100KL; Partial_Alternate_Internal_Part_Number: MCD-03301; Order_Code_RS: 2421891; Component_Country_Of_Origin: China; ShowFields: YES; ID: 2533
R217 = MCD-00062: Resistor, 330R, 0402, +/-1%, 1/16W; Manufacturer_Part_Number: RC0402FR-07330RL; Manufacturer: YAGEO; Part_Preference: Recommended; Order_Code_RS: 9239170; Component_Country_Of_Origin: China; ShowFields: YES; ID: 2529
R228 R229 = MCD-00387: Resistor, 1M3, 0402, +/-1%, 1/16W; Part_Preference: Recommended; Manufacturer: YAGEO; Manufacturer_Part_Number: RC0402FR-071M3L; Component_Country_Of_Origin: China; ShowFields: YES; ID: 2893
SB46 SB48 = MCD-00071: as SB4 on sheet STM32_microcontroller_power
SB47 = MCD-00071: Resistor, 0R, SB0603, 5%, 0.1W; Part_Preference: Recommended; Manufacturer: YAGEO; Manufacturer_Part_Number: RC0603JR-070RL; Manufacturer_HQ_COO: Unknown; ShowFields: YES; ID: 2521; Order_Code_RS: 199-5647; Component_Country_Of_Origin: China
U46 = MCD-02130: IC, USB Type-C Protection for DRP applications Dual Role Power; Manufacturer: STMICROELECTRONICS; Part_Preference: Recommended; Manufacturer_HQ_COO: EU; Component_Country_Of_Origin: China; ShowFields: YES; ID: 4230
U50 = MCD-01207: Diode, ESD TVS, 22V, 200nA, 25V8, QFN1610; Manufacturer: STMICROELECTRONICS; BMS_Part_Number: 9179045; Part_Preference: Recommended; Manufacturer_HQ_COO: EU; Component_Country_Of_Origin: China; ShowFields: YES; ID: 3289; Order_Code_RS: 163-9774
U51 = MCD-03060: IC, ESD protection and Common Filter High Speed serial Interfaces, 10.7 GHz; Part_Preference: Recommended; Manufacturer: STMICROELECTRONICS; Component_Country_Of_Origin: China; ShowFields: YES; ID: 5176

## Sheet Camera.SchDoc: MB1854
size A4; Date: Not used; ApprovedBy: Not used; CheckedBy: Not used; Author: Not used; CompanyName: STMicroelectronics; DrawnBy: Not used; Engineer: Not used; Organization: Not used; Address1: Not used; Address2: Not used; Address3: Not used; Address4: Not used; DocumentNumber: Not used; Revision: Not used; SheetNumber: 12; SheetTotal: 21
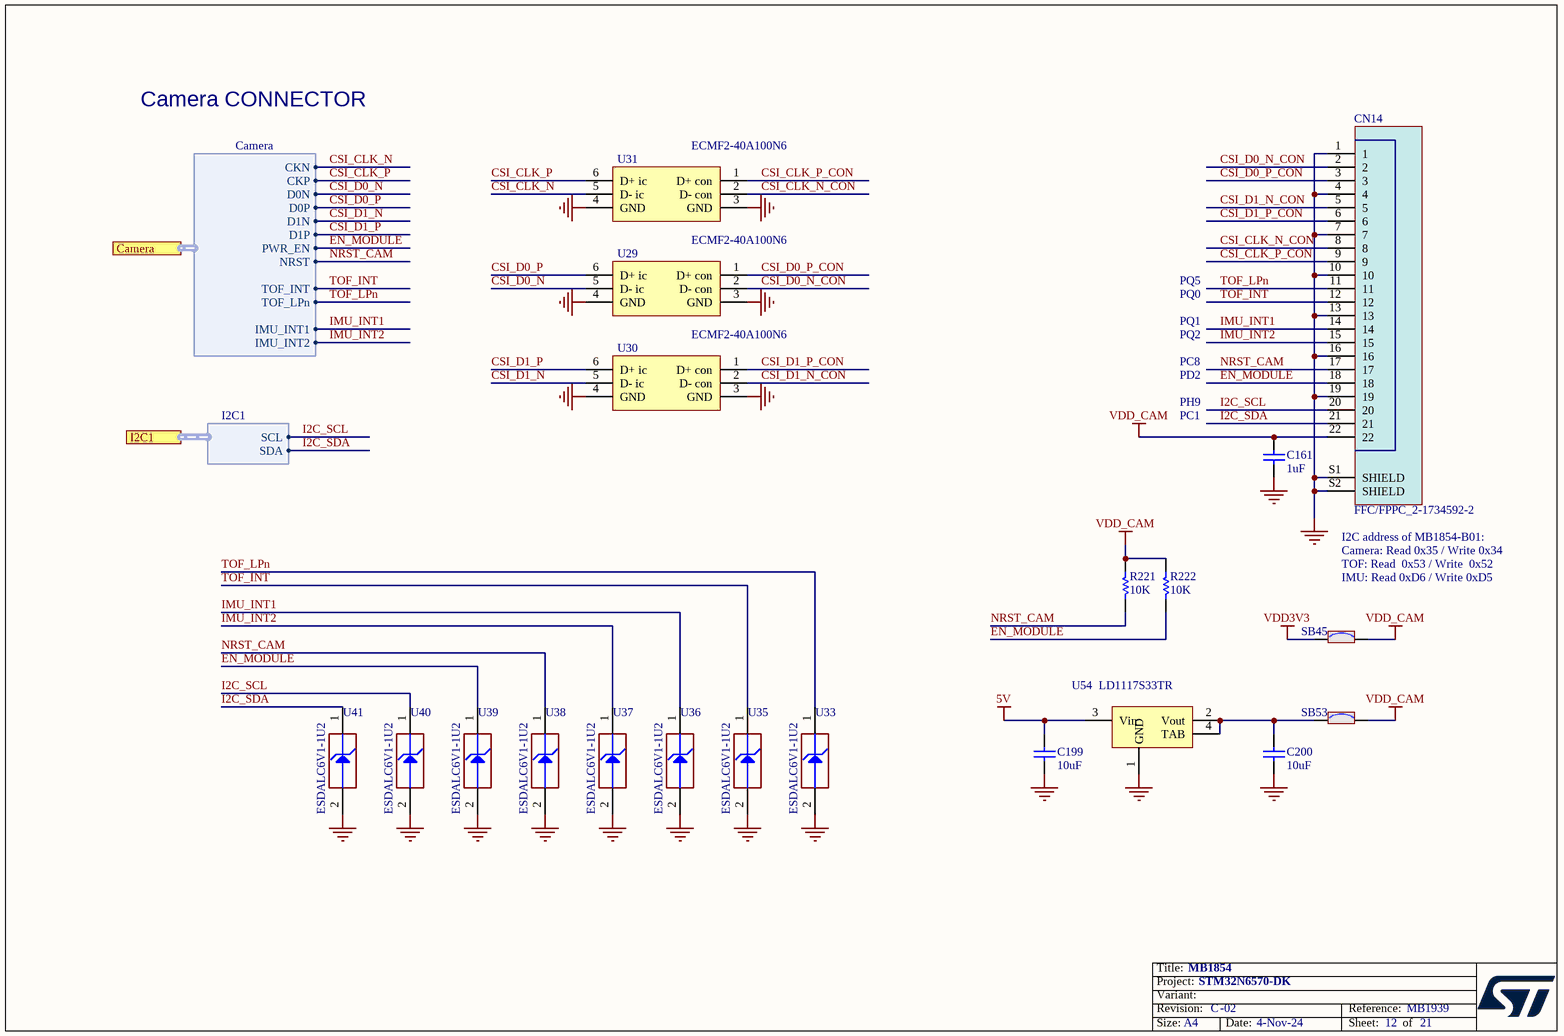
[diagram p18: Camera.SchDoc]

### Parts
C161  value 1uF  [C0402]  (hidden comment: Capacitor)
C199  value 10uF  [C0805]  (hidden comment: Capacitor)
C200  value 10uF  [C0805]  (hidden comment: Capacitor)
CN14  value FFC/FPPC_2-1734592-2  [CON_TE-CONNECTIVITY_2-1734592-2_INV]  (hidden comment: 2-1734592-2)
R221  value 10K  [R0402]  (hidden comment: Resistor)
R222  value 10K  [R0402]  (hidden comment: Resistor)
SB45  SB_ON  [SOLDER-BRIDGE_R0603-0R]  (value not drawn)
SB53  SB_ON  [SOLDER-BRIDGE_R0603-0R]  (value not drawn)
U29  ECMF2-40A100N6  [ESD_UQFN-6L_1P45X1P4_P040]
U30  ECMF2-40A100N6  [ESD_UQFN-6L_1P45X1P4_P040]
U31  ECMF2-40A100N6  [ESD_UQFN-6L_1P45X1P4_P040]
U33  value ESDALC6V1-1U2  [ESD_ST0201]  (hidden comment: ESD-TRANSIL)
U35  value ESDALC6V1-1U2  [ESD_ST0201]  (hidden comment: ESD-TRANSIL)
U36  value ESDALC6V1-1U2  [ESD_ST0201]  (hidden comment: ESD-TRANSIL)
U37  value ESDALC6V1-1U2  [ESD_ST0201]  (hidden comment: ESD-TRANSIL)
U38  value ESDALC6V1-1U2  [ESD_ST0201]  (hidden comment: ESD-TRANSIL)
U39  value ESDALC6V1-1U2  [ESD_ST0201]  (hidden comment: ESD-TRANSIL)
U40  value ESDALC6V1-1U2  [ESD_ST0201]  (hidden comment: ESD-TRANSIL)
U41  value ESDALC6V1-1U2  [ESD_ST0201]  (hidden comment: ESD-TRANSIL)
U54  LD1117S33TR  [REG_SOT223-TAB]

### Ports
Camera (harness Camera), I2C1 (harness I2C1)

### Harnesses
Camera: CKN, CKP, D0N, D0P, D1N, D1P, PWR_EN, NRST, TOF_INT, TOF_LPn, IMU_INT1, IMU_INT2
I2C1: SCL, SDA

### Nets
5V: C199.2 U54.3(Vin)
GND: C161.1 C199.1 C200.1 CN14.1 CN14.4 CN14.7 CN14.10 CN14.13 CN14.16 CN14.19 CN14.S1(SHIELD) CN14.S2(SHIELD) U29.3(GND) U29.4(GND) U30.3(GND) U30.4(GND) U31.3(GND) U31.4(GND) U33.2(GND) U35.2(GND) U36.2(GND) U37.2(GND) U38.2(GND) U39.2(GND) U40.2(GND) U41.2(GND) U54.1(GND)
VDD3V3: SB45.1
VDD_CAM: C161.2 CN14.22 R221.1 R222.1 SB45.2 SB53.2
CSI_CLK_N: U31.5(D-_ic) ; port Camera.CKN  [project net CSI_CKN]
CSI_CLK_N_CON: CN14.8 U31.2(D-_con)
CSI_CLK_P: U31.6(D+_ic) ; port Camera.CKP  [project net CSI_CKP]
CSI_CLK_P_CON: CN14.9 U31.1(D+_con)
CSI_D0_N: U29.5(D-_ic) ; port Camera.D0N
CSI_D0_N_CON: CN14.2 U29.2(D-_con)
CSI_D0_P: U29.6(D+_ic) ; port Camera.D0P
CSI_D0_P_CON: CN14.3 U29.1(D+_con)
CSI_D1_N: U30.5(D-_ic) ; port Camera.D1N
CSI_D1_N_CON: CN14.5 U30.2(D-_con)
CSI_D1_P: U30.6(D+_ic) ; port Camera.D1P
CSI_D1_P_CON: CN14.6 U30.1(D+_con)
EN_MODULE: CN14.18 R222.2 U39.1(IO1) ; port Camera.PWR_EN
I2C_SCL: CN14.20 U40.1(IO1) ; port I2C1.SCL  [project net ARD_D15]
I2C_SDA: CN14.21 U41.1(IO1) ; port I2C1.SDA  [project net ARD_D14]
IMU_INT1: CN14.14 U36.1(IO1) ; port Camera.IMU_INT1
IMU_INT2: CN14.15 U37.1(IO1) ; port Camera.IMU_INT2
NRST_CAM: CN14.17 R221.2 U38.1(IO1) ; port Camera.NRST
TOF_INT: CN14.12 U35.1(IO1) ; port Camera.TOF_INT  [project net PQ0]
TOF_LPn: CN14.11 U33.1(IO1) ; port Camera.TOF_LPn  [project net PQ5]
NetC200_2: C200.2 SB53.1 U54.2(Vout) U54.4(TAB)

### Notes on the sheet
- Camera CONNECTOR
- PQ5
- PQ0
- PC8
- PD2
- PQ1
- PQ2
- PH9
- PC1
- (near CN14) I2C address of MB1854-B01:
- Camera: Read 0x35 / Write 0x34
- TOF: Read  0x53 / Write  0x52
- IMU: Read 0xD6 / Write 0xD5

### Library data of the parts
C161 = MCD-00095: Capacitor, MLCC, 1uF, 25V, X5R, +/-10%, 0402, T=0.5mm; Manufacturer_Part_Number: GRM155R61E105KA12; Manufacturer: MURATA; Part_Preference: Recommended; Partial_Alternate_Internal_Part_Number: MCD-04188; Order_Code_RS: 2218855; Component_Country_Of_Origin: Japan°°; ID: 2772; ShowFields: YES
C199 C200 = MCD-00014: Capacitor, MLCC, 10uF, 25V, X5R, +/-10%, 0805, T=0.85mm; Manufacturer_Part_Number: CC0805KRX5R8BB106; Manufacturer: YAGEO; Part_Preference: Recommended; Full_Alternate_Internal_Part_Number: MCD-02385; Partial_Alternate_Internal_Part_Number: MCD-03053; Component_Country_Of_Origin: China; ShowFields: YES; ID: 2468
CN14 = MCD-03600: Socket_FFC/FPC, 22pins, 0.5mm, RA, SMD, T=2mm; Part_Type: Connector; Part_Preference: Recommended; Manufacturer: TE CONNECTIVITY; Component_Country_Of_Origin: China°; ShowFields: YES; ID: 5716
R221 R222 = MCD-00053: as R197 on sheet USB1_DRP
SB45 SB53 = MCD-00071: Resistor, 0R, SB0603, 5%, 0.1W; Manufacturer_Part_Number: RC0603JR-070RL; Manufacturer: YAGEO; Part_Preference: Recommended; Manufacturer_HQ_COO: Unknown; Order_Code_RS: 199-5647; Component_Country_Of_Origin: China; ShowFields: YES; ID: 2521
U29-U31 = MCD-03060: as U51 on sheet USB1_DRP
U33 U35-U41 = MCD-00170: Diode, ESD TVS, 3V, 100nA, 8V, ST0201; BMS_Part_Number: 9151132; Part_Preference: Recommended; Manufacturer: STMICROELECTRONICS; Manufacturer_HQ_COO: EU; Component_Country_Of_Origin: China; ShowFields: YES; ID: 2696; Order_Code_RS: 795-8404
U54 = MCD-00089: LDO, Adjustable and fixed low drop positive voltage regulator; Part_Type: IC; Manufacturer: STMICROELECTRONICS; BMS_Part_Number: 9176186; Part_Preference: Recommended; Manufacturer_HQ_COO: EU; Partial_Alternate_Internal_Part_Number: MCD-02764; Component_Country_Of_Origin: China; ShowFields: YES; ID: 2504; Order_Code_RS: 168-6804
